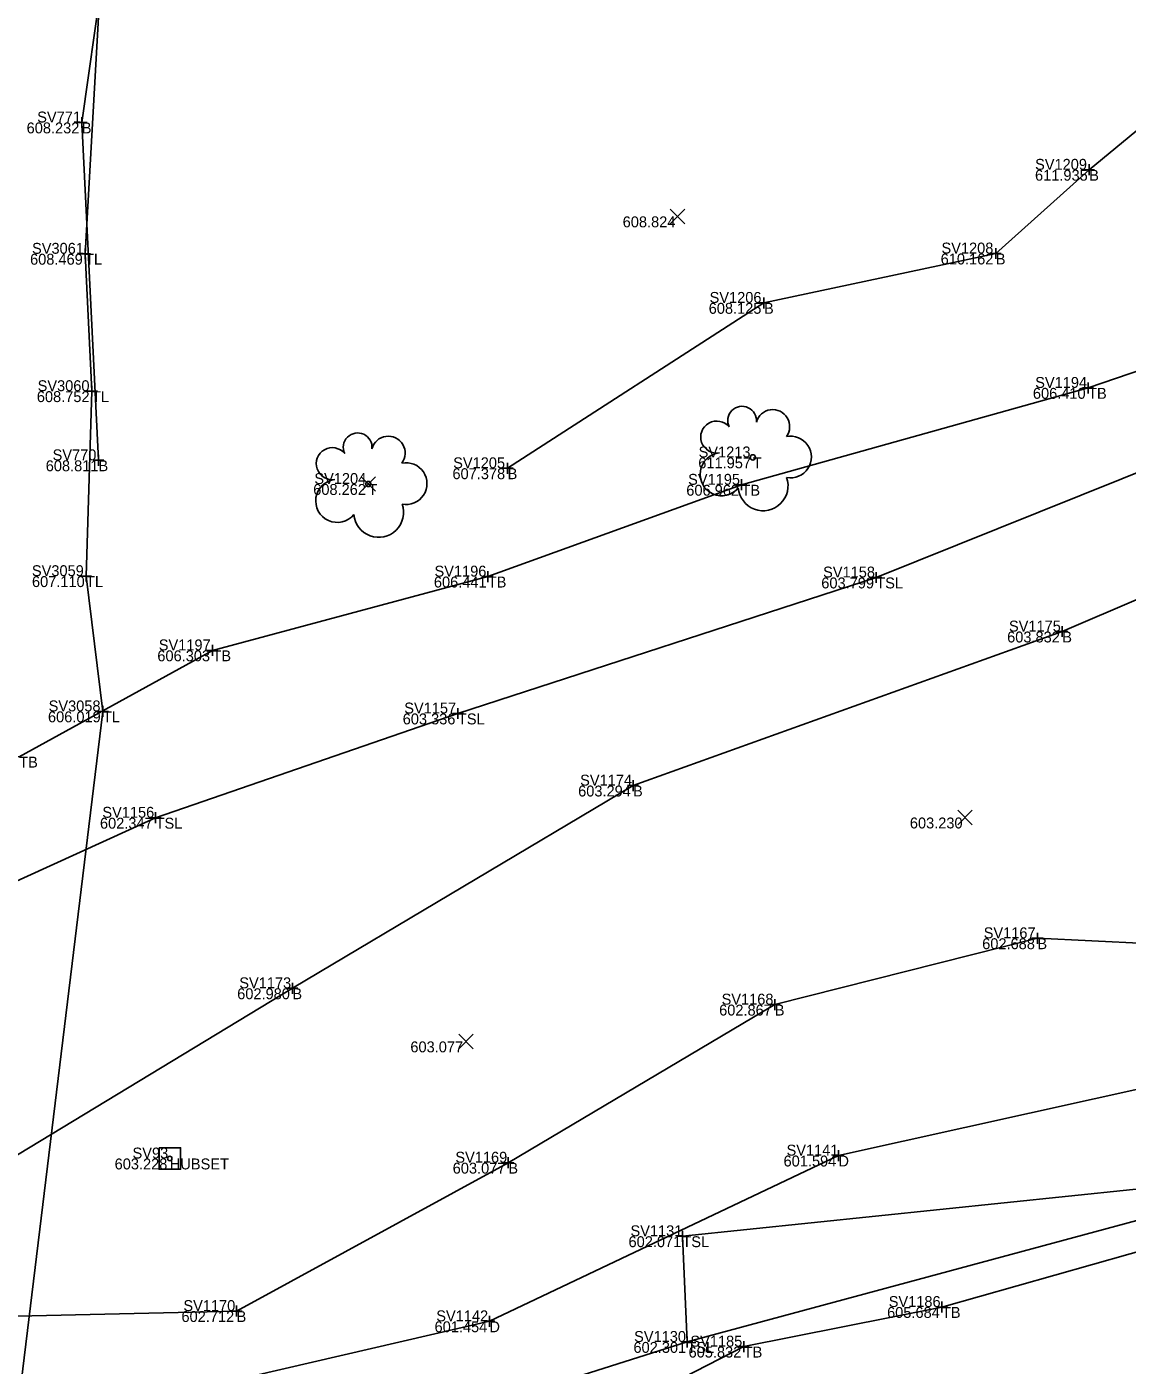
# Model space of a CAD drawing. Extents: x -2 to 1979875, y -2 to 232027.
# Drawn here: x 1978801.8 to 1978852.3, y 231261.4 to 231322.8 of the extents above; entities that cross this region are included whole.
import ezdxf

# ---------------------------------------------------------------- set-up
doc = ezdxf.new("R2010")
doc.units = 0
for name, color, linetype in [('_CIVIL_CONSTRUCTION', 7, 'Continuous'), ('DR_X_Ditch', 7, 'Continuous'), ('GE_P_Alignment', 7, 'Continuous'), ('GE_P_Alignment_1000_Curve_Data', 7, 'Continuous'), ('GE_X_Alignment', 7, 'Continuous'), ('GE_X_Alignment_100_Curve_Data', 7, 'Continuous'), ('GE_X_Alignment_100_Stations', 7, 'Continuous'), ('HY_X_Water_Edge', 7, 'Continuous'), ('SV_P_Control_Cells_Set', 7, 'Continuous'), ('SV_X_Random_Point', 7, 'Continuous'), ('SV_X_Toe_of_Slope', 7, 'Continuous'), ('SV_X_Top_of_Bank', 7, 'Continuous'), ('VG_X_Cells', 7, 'Continuous')]:
    doc.layers.add(name, color=color, linetype=linetype)

msp = doc.modelspace()

# ---------------------------------------------------------------- linework, layer by layer
at = {"layer": 'DR_X_Ditch'}
msp.add_lwpolyline([(1978888.584, 231299.627), (1978879.993, 231287.447), (1978870.172, 231277.213), (1978856.534, 231274.917), (1978839.012, 231271.025), (1978823.007, 231263.425), (1978802.617, 231258.705), (1978787.259, 231269.564)], dxfattribs=at)
at = {"layer": 'GE_P_Alignment'}
for points in [[(1978805.078, 231302.902), (1978804.312, 231318.393), (1978807.025, 231337.482), (1978807.608, 231347.62), (1978815.872, 231349.445), (1978830.429, 231348.066), (1978839.191, 231344.012), (1978846.269, 231348.737), (1978841.316, 231369.431), (1978838.009, 231386.763), (1978837.276, 231409.505), (1978850.642, 231428.207)], [(1978823.841, 231302.538), (1978835.598, 231310.121), (1978846.229, 231312.385), (1978850.512, 231316.224), (1978859.326, 231323.503), (1978863.746, 231327.737), (1978864.641, 231332.322)], [(1978880.582, 231316.673), (1978878.73, 231308.205), (1978871.111, 231292.475), (1978865.586, 231280.144), (1978848.135, 231280.988), (1978836.093, 231277.946), (1978823.874, 231270.699), (1978811.412, 231263.896), (1978801.351, 231263.66), (1978797.393, 231268.655), (1978813.97, 231278.694), (1978829.592, 231287.989), (1978849.277, 231295.052), (1978867.627, 231302.914), (1978876.642, 231308.974)]]:
    msp.add_lwpolyline(points, dxfattribs=at)
at = {"layer": 'GE_P_Alignment_1000_Curve_Data'}
msp.add_lwpolyline([(1978800.253, 231250.204), (1978805.284, 231291.391), (1978804.508, 231297.592), (1978804.78, 231306.073), (1978804.463, 231312.372), (1978805.146, 231324.315), (1978805.161, 231336.373), (1978807.189, 231350.111), (1978807.848, 231360.671), (1978809.086, 231373.348), (1978811.125, 231382.982), (1978814.162, 231421.098), (1978816.965, 231468.048), (1978822.427, 231510.515)], dxfattribs=at)
at = {"layer": 'GE_X_Alignment_100_Curve_Data'}
for p, q in [((1978804.312, 231318.643), (1978804.312, 231318.143)), ((1978804.062, 231318.393), (1978804.562, 231318.393)), ((1978804.312, 231318.393), (1978804.312, 231318.393)), ((1978850.262, 231316.224), (1978850.762, 231316.224)), ((1978850.512, 231316.474), (1978850.512, 231315.974)), ((1978850.512, 231316.224), (1978850.512, 231316.224)), ((1978804.463, 231312.622), (1978804.463, 231312.122)), ((1978846.229, 231312.635), (1978846.229, 231312.135)), ((1978804.213, 231312.372), (1978804.713, 231312.372)), ((1978804.463, 231312.372), (1978804.463, 231312.372)), ((1978845.979, 231312.385), (1978846.479, 231312.385)), ((1978846.229, 231312.385), (1978846.229, 231312.385)), ((1978835.348, 231310.121), (1978835.848, 231310.121)), ((1978835.598, 231310.371), (1978835.598, 231309.871)), ((1978835.598, 231310.121), (1978835.598, 231310.121)), ((1978804.78, 231306.323), (1978804.78, 231305.823)), ((1978850.46, 231306.473), (1978850.46, 231305.973)), ((1978804.53, 231306.073), (1978805.03, 231306.073)), ((1978804.78, 231306.073), (1978804.78, 231306.073)), ((1978850.21, 231306.223), (1978850.71, 231306.223)), ((1978850.46, 231306.223), (1978850.46, 231306.223)), ((1978804.828, 231302.902), (1978805.328, 231302.902)), ((1978805.078, 231303.152), (1978805.078, 231302.652)), ((1978805.078, 231302.902), (1978805.078, 231302.902)), ((1978823.841, 231302.788), (1978823.841, 231302.288)), ((1978823.591, 231302.538), (1978824.091, 231302.538)), ((1978823.841, 231302.538), (1978823.841, 231302.538)), ((1978834.564, 231302.031), (1978834.564, 231301.531)), ((1978834.314, 231301.781), (1978834.814, 231301.781)), ((1978834.564, 231301.781), (1978834.564, 231301.781)), ((1978804.508, 231297.842), (1978804.508, 231297.342)), ((1978822.93, 231297.821), (1978822.93, 231297.321)), ((1978840.747, 231297.78), (1978840.747, 231297.28)), ((1978804.258, 231297.592), (1978804.758, 231297.592)), ((1978804.508, 231297.592), (1978804.508, 231297.592)), ((1978822.68, 231297.571), (1978823.18, 231297.571)), ((1978822.93, 231297.571), (1978822.93, 231297.571)), ((1978840.497, 231297.53), (1978840.997, 231297.53)), ((1978840.747, 231297.53), (1978840.747, 231297.53)), ((1978849.277, 231295.302), (1978849.277, 231294.802)), ((1978849.027, 231295.052), (1978849.527, 231295.052)), ((1978849.277, 231295.052), (1978849.277, 231295.052)), ((1978810.054, 231294.189), (1978810.554, 231294.189)), ((1978810.304, 231294.439), (1978810.304, 231293.939)), ((1978810.304, 231294.189), (1978810.304, 231294.189)), ((1978805.284, 231291.641), (1978805.284, 231291.141)), ((1978821.562, 231291.545), (1978821.562, 231291.045)), ((1978805.034, 231291.391), (1978805.534, 231291.391)), ((1978805.284, 231291.391), (1978805.284, 231291.391)), ((1978821.312, 231291.295), (1978821.812, 231291.295)), ((1978821.562, 231291.295), (1978821.562, 231291.295)), ((1978829.342, 231287.989), (1978829.842, 231287.989)), ((1978829.592, 231288.239), (1978829.592, 231287.739)), ((1978829.592, 231287.989), (1978829.592, 231287.989)), ((1978807.698, 231286.764), (1978807.698, 231286.264)), ((1978807.448, 231286.514), (1978807.948, 231286.514)), ((1978807.698, 231286.514), (1978807.698, 231286.514)), ((1978848.135, 231281.238), (1978848.135, 231280.738)), ((1978847.885, 231280.988), (1978848.385, 231280.988)), ((1978848.135, 231280.988), (1978848.135, 231280.988)), ((1978813.72, 231278.694), (1978814.22, 231278.694)), ((1978813.97, 231278.944), (1978813.97, 231278.444)), ((1978813.97, 231278.694), (1978813.97, 231278.694)), ((1978836.093, 231278.196), (1978836.093, 231277.696)), ((1978835.843, 231277.946), (1978836.343, 231277.946)), ((1978836.093, 231277.946), (1978836.093, 231277.946)), ((1978823.624, 231270.699), (1978824.124, 231270.699)), ((1978823.874, 231270.949), (1978823.874, 231270.449)), ((1978823.874, 231270.699), (1978823.874, 231270.699)), ((1978838.762, 231271.025), (1978839.262, 231271.025)), ((1978839.012, 231271.275), (1978839.012, 231270.775)), ((1978839.012, 231271.025), (1978839.012, 231271.025)), ((1978831.606, 231267.326), (1978832.106, 231267.326)), ((1978831.856, 231267.576), (1978831.856, 231267.076)), ((1978831.856, 231267.326), (1978831.856, 231267.326)), ((1978811.412, 231264.146), (1978811.412, 231263.646)), ((1978843.51, 231264.082), (1978844.01, 231264.082)), ((1978843.76, 231264.332), (1978843.76, 231263.832)), ((1978843.76, 231264.082), (1978843.76, 231264.082)), ((1978811.162, 231263.896), (1978811.662, 231263.896)), ((1978811.412, 231263.896), (1978811.412, 231263.896)), ((1978822.757, 231263.425), (1978823.257, 231263.425)), ((1978823.007, 231263.675), (1978823.007, 231263.175)), ((1978823.007, 231263.425), (1978823.007, 231263.425)), ((1978832.082, 231262.729), (1978832.082, 231262.229)), ((1978831.832, 231262.479), (1978832.332, 231262.479)), ((1978832.082, 231262.479), (1978832.082, 231262.479)), ((1978834.418, 231262.265), (1978834.918, 231262.265)), ((1978834.668, 231262.515), (1978834.668, 231262.015)), ((1978834.668, 231262.265), (1978834.668, 231262.265))]:
    msp.add_line(p, q, dxfattribs=at)
at = {"layer": 'HY_X_Water_Edge'}
for points in [[(1978738.528, 231278.008), (1978757.257, 231280.755), (1978763.371, 231281.556), (1978784.159, 231284.036), (1978793.351, 231279.988), (1978807.698, 231286.514), (1978821.562, 231291.295), (1978840.747, 231297.53), (1978857.609, 231304.298), (1978872.974, 231309.553), (1978877.125, 231314.237), (1978883.495, 231319.371), (1978882.175, 231341.325), (1978883.048, 231360.363), (1978875.551, 231375.847), (1978868.903, 231394.228), (1978864.235, 231416.891), (1978862.047, 231444.318), (1978861.234, 231465.995)], [(1978817.09, 231257.737), (1978832.082, 231262.479), (1978861.367, 231270.387), (1978875.304, 231272.806), (1978884.386, 231282.392), (1978891.721, 231292.42), (1978901.115, 231305.262)]]:
    msp.add_lwpolyline(points, dxfattribs=at)
at = {"layer": 'SV_P_Control_Cells_Set'}
msp.add_lwpolyline([(1978807.855, 231271.387), (1978808.845, 231271.387), (1978808.845, 231270.396), (1978807.855, 231270.396), (1978807.855, 231271.387)], dxfattribs=at)
msp.add_lwpolyline([(1978807.855, 231271.387), (1978808.845, 231271.387), (1978808.845, 231270.396), (1978807.855, 231270.396), (1978807.855, 231271.387)], dxfattribs=at)
msp.add_circle((1978808.35, 231270.891), 0.1, dxfattribs=at)
msp.add_circle((1978808.35, 231270.891), 0.1, dxfattribs=at)
at = {"layer": 'SV_X_Random_Point'}
for p, q in [((1978831.301, 231313.752), (1978831.967, 231314.42)), ((1978831.301, 231314.42), (1978831.967, 231313.752)), ((1978817.122, 231301.483), (1978817.788, 231302.151)), ((1978817.122, 231302.151), (1978817.788, 231301.483)), ((1978844.485, 231286.191), (1978845.151, 231286.859)), ((1978844.485, 231286.859), (1978845.151, 231286.191)), ((1978821.6, 231275.925), (1978822.266, 231276.593)), ((1978821.6, 231276.593), (1978822.266, 231275.925))]:
    msp.add_line(p, q, dxfattribs=at)
at = {"layer": 'SV_X_Toe_of_Slope'}
for points in [[(1978783.289, 231254.287), (1978787.737, 231256.586), (1978799.967, 231256.811), (1978817.09, 231257.737), (1978832.082, 231262.479), (1978831.856, 231267.326), (1978861.367, 231270.387), (1978875.304, 231272.806), (1978884.386, 231282.392), (1978891.721, 231292.42), (1978902.966, 231322.566)], [(1978784.159, 231284.036), (1978793.351, 231279.988), (1978807.698, 231286.514), (1978821.562, 231291.295), (1978840.747, 231297.53), (1978857.609, 231304.298), (1978872.974, 231309.553), (1978877.125, 231314.237), (1978878.34, 231321.237)]]:
    msp.add_lwpolyline(points, dxfattribs=at)
at = {"layer": 'SV_X_Top_of_Bank'}
for points in [[(1978874.834, 231321.265), (1978869.013, 231312.553), (1978850.46, 231306.223), (1978834.564, 231301.781), (1978822.93, 231297.571), (1978810.304, 231294.189), (1978801.442, 231289.314), (1978795.097, 231290.638)], [(1978792.729, 231249.351), (1978802.059, 231250.56), (1978809.026, 231251.174), (1978824.702, 231257.152), (1978834.668, 231262.265), (1978843.76, 231264.082), (1978857.569, 231267.988), (1978870.834, 231267.898), (1978882.845, 231275.772), (1978894.192, 231280.826), (1978903.719, 231297.628)]]:
    msp.add_lwpolyline(points, dxfattribs=at)
at = {"layer": 'VG_X_Cells'}
for centre in [(1978835.086, 231303.036), (1978817.455, 231301.817)]:
    msp.add_circle(centre, 0.12, dxfattribs=at)
for centre, radius, start, end in [((1978834.594, 231304.72), 0.658, 354.0047, 205.97412), ((1978835.999, 231304.451), 0.776, 323.82996, 165.0376), ((1978833.431, 231303.968), 0.735, 39.06254, 279.54124), ((1978816.963, 231303.501), 0.658, 354.0047, 205.97412), ((1978818.368, 231303.232), 0.776, 323.82996, 165.0376), ((1978836.816, 231303.054), 0.957, 259.14531, 101.45961), ((1978815.8, 231302.749), 0.735, 39.06254, 279.54124), ((1978833.659, 231302.262), 0.987, 96.17219, 320.57371), ((1978819.185, 231301.835), 0.957, 259.14531, 101.45961), ((1978816.028, 231301.043), 0.987, 96.17219, 320.57371), ((1978835.559, 231301.733), 1.142, 184.94757, 19.45715), ((1978817.928, 231300.514), 1.142, 184.94757, 19.45715)]:
    msp.add_arc(centre, radius, start, end, dxfattribs=at)

# ---------------------------------------------------------------- texts
at = {"layer": '_CIVIL_CONSTRUCTION'}
for s, p in [('608.232', (1978801.784, 231317.893)), ('611.935', (1978848.028, 231315.724)), ('608.824', (1978829.118, 231313.586)), ('608.469', (1978801.942, 231311.872)), ('610.162', (1978843.701, 231311.885)), ('608.125', (1978833.063, 231309.621)), ('608.752', (1978802.252, 231305.573)), ('606.410', (1978847.93, 231305.723)), ('608.811', (1978802.66, 231302.402)), ('611.957', (1978832.586, 231302.536)), ('607.378', (1978821.311, 231302.038)), ('608.262', (1978814.927, 231301.317)), ('608.262', (1978814.927, 231301.317)), ('606.962', (1978832.036, 231301.281)), ('607.110', (1978802.029, 231297.092)), ('606.441', (1978820.46, 231297.071)), ('603.799', (1978838.226, 231297.03)), ('603.832', (1978846.749, 231294.552)), ('606.303', (1978807.779, 231293.689)), ('606.019', (1978802.763, 231290.891)), ('603.336', (1978819.03, 231290.795)), ('603.294', (1978827.076, 231287.489)), ('602.347', (1978805.147, 231286.014)), ('603.230', (1978842.288, 231286.025)), ('602.688', (1978845.605, 231280.488)), ('602.980', (1978811.44, 231278.194)), ('602.867', (1978833.542, 231277.446)), ('603.077', (1978819.382, 231275.759)), ('603.228', (1978805.82, 231270.391)), ('603.228', (1978805.82, 231270.391)), ('603.077', (1978821.323, 231270.199)), ('601.594', (1978836.496, 231270.525)), ('602.071', (1978829.386, 231266.826)), ('605.684', (1978841.244, 231263.582)), ('602.712', (1978808.884, 231263.396)), ('601.454', (1978820.491, 231262.925)), ('602.301', (1978829.612, 231261.979)), ('605.832', (1978832.14, 231261.765))]:
    msp.add_text(s, height=0.5, dxfattribs=at).set_placement(p)
at = {"layer": 'GE_X_Alignment'}
for s, p in [('SV771', (1978802.269, 231318.393)), ('SV1209', (1978848.03, 231316.224)), ('SV3061', (1978802.031, 231312.372)), ('SV1208', (1978843.738, 231312.385)), ('SV1206', (1978833.104, 231310.121)), ('SV3060', (1978802.288, 231306.073)), ('SV1194', (1978848.035, 231306.223)), ('SV770', (1978802.974, 231302.902)), ('SV1213', (1978832.6, 231303.036)), ('SV1205', (1978821.344, 231302.538)), ('SV1204', (1978814.978, 231301.817)), ('SV1195', (1978832.119, 231301.781)), ('SV3059', (1978802.026, 231297.592)), ('SV1196', (1978820.488, 231297.571)), ('SV1158', (1978838.308, 231297.53)), ('SV1175', (1978846.832, 231295.052)), ('SV1197', (1978807.843, 231294.189)), ('SV3058', (1978802.793, 231291.391)), ('SV1157', (1978819.101, 231291.295)), ('SV1174', (1978827.167, 231287.989)), ('SV1156', (1978805.256, 231286.514)), ('SV1167', (1978845.674, 231280.988)), ('SV1173', (1978811.536, 231278.694)), ('SV1168', (1978833.654, 231277.946)), ('SV93', (1978806.64, 231270.891)), ('SV93', (1978806.64, 231270.891)), ('SV1141', (1978836.632, 231271.025)), ('SV1169', (1978821.444, 231270.699)), ('SV1131', (1978829.476, 231267.326)), ('SV1186', (1978841.318, 231264.082)), ('SV1170', (1978808.972, 231263.896)), ('SV1142', (1978820.569, 231263.425)), ('SV1130', (1978829.642, 231262.479)), ('SV1185', (1978832.223, 231262.265))]:
    msp.add_text(s, height=0.5, dxfattribs=at).set_placement(p)
at = {"layer": 'GE_X_Alignment_100_Stations'}
for s, p in [('B', (1978804.312, 231317.893)), ('B', (1978850.512, 231315.724)), ('TL', (1978804.463, 231311.872)), ('B', (1978846.229, 231311.885)), ('B', (1978835.598, 231309.621)), ('TL', (1978804.78, 231305.573)), ('TB', (1978850.46, 231305.723)), ('B', (1978805.078, 231302.402)), ('T', (1978835.086, 231302.536)), ('B', (1978823.841, 231302.038)), ('T', (1978817.455, 231301.317)), ('TB', (1978834.564, 231301.281)), ('TL', (1978804.508, 231297.092)), ('TB', (1978822.93, 231297.071)), ('TSL', (1978840.747, 231297.03)), ('B', (1978849.277, 231294.552)), ('TB', (1978810.304, 231293.689)), ('TL', (1978805.284, 231290.891)), ('TSL', (1978821.562, 231290.795)), ('TB', (1978801.442, 231288.814)), ('B', (1978829.592, 231287.489)), ('TSL', (1978807.698, 231286.014)), ('B', (1978848.135, 231280.488)), ('B', (1978813.97, 231278.194)), ('B', (1978836.093, 231277.446)), ('HUBSET', (1978808.35, 231270.391)), ('HUBSET', (1978808.35, 231270.391)), ('B', (1978823.874, 231270.199)), ('D', (1978839.012, 231270.525)), ('TSL', (1978831.856, 231266.826)), ('TB', (1978843.76, 231263.582)), ('B', (1978811.412, 231263.396)), ('D', (1978823.007, 231262.925)), ('TSL', (1978832.082, 231261.979)), ('TB', (1978834.668, 231261.765))]:
    msp.add_text(s, height=0.5, dxfattribs=at).set_placement(p)

doc.saveas('drawing.dxf')
